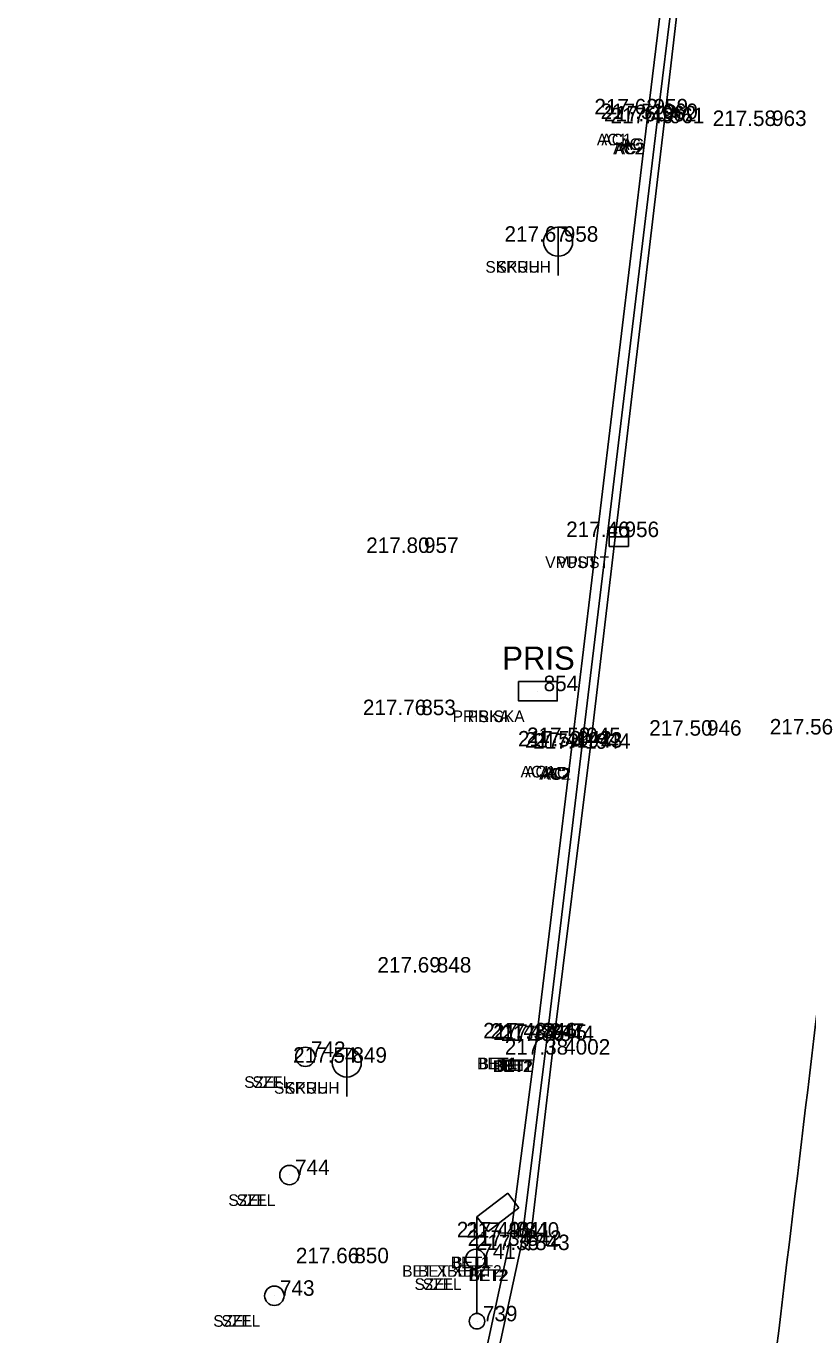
# Model space of a CAD drawing. Extents: x -471047 to -470889, y -1102859 to -1102000.
# Drawn here: x -471002.78 to -470982.59, y -1102598.73 to -1102564.92 of the extents above; entities that cross this region are included whole.
import ezdxf

# ---------------------------------------------------------------- set-up
doc = ezdxf.new("R2010")
doc.units = 0
for name, color, linetype in [('Vrstva 1', 7, 'Continuous'), ('Vrstva 23', 7, 'Continuous'), ('Vrstva 25', 7, 'Continuous'), ('Vrstva 34', 7, 'Continuous'), ('Vrstva 35', 7, 'Continuous'), ('Vrstva 36', 7, 'Continuous'), ('Vrstva 38', 7, 'Continuous'), ('Vrstva 5', 7, 'Continuous'), ('Vrstva 7', 7, 'Continuous'), ('Vrstva 8', 7, 'Continuous')]:
    doc.layers.add(name, color=color, linetype=linetype)

msp = doc.modelspace()

# ---------------------------------------------------------------- linework, layer by layer
at = {"layer": 'Vrstva 1'}
for points in [[(-471040.344, -1102858.385), (-471031.676, -1102846.187), (-471026.357, -1102838.629), (-471023.212, -1102833.975), (-471019.21, -1102827.465), (-471016.861, -1102823.272), (-471013.099, -1102815.912), (-471010.824, -1102810.955), (-471007.329, -1102802.292), (-471005.34, -1102796.515), (-471002.842, -1102787.838), (-471001.3, -1102780.997), (-471000.19, -1102774.713), (-470999.247, -1102768.204), (-470998.794, -1102764.784), (-470997.199, -1102751.812), (-470994.899, -1102732.807), (-470992.551, -1102713.262), (-470990.326, -1102694.887), (-470988.122, -1102676.57), (-470985.812, -1102657.305), (-470983.537, -1102638.407), (-470981.386, -1102620.622), (-470979.843, -1102608.014), (-470976.377, -1102579.253), (-470972.945, -1102550.69), (-470970.475, -1102530.206), (-470967.905, -1102508.801), (-470965.053, -1102485.131), (-470962.734, -1102465.9), (-470960.173, -1102444.812), (-470957.795, -1102425.103), (-470954.965, -1102401.839), (-470953.834, -1102392.574), (-470952.33, -1102379.985), (-470950.744, -1102366.853), (-470948.978, -1102352.106), (-470947.037, -1102335.844), (-470944.949, -1102318.462), (-470944.013, -1102310.745), (-470942.39, -1102297.267), (-470939.519, -1102273.45), (-470937.593, -1102257.43), (-470936.064, -1102244.81), (-470934.114, -1102228.634), (-470931.621, -1102207.856), (-470929.536, -1102190.857), (-470926.572, -1102166.31), (-470924.91, -1102152.663), (-470923.413, -1102140.333), (-470921.923, -1102127.669), (-470921.155, -1102120.084), (-470920.446, -1102109.574), (-470919.912, -1102099.137), (-470919.63, -1102088.981), (-470919.523, -1102081.193), (-470919.563, -1102070.395), (-470919.714, -1102064.236), (-470920.134, -1102054.704), (-470920.462, -1102047.615), (-470920.599, -1102044.52), (-470920.743, -1102041.873), (-470921.125, -1102034.455), (-470921.774, -1102030.337), (-470922.418, -1102027.787), (-470923.734, -1102023.93), (-470924.872, -1102021.434), (-470926.752, -1102018.182), (-470927.953, -1102016.45), (-470929.616, -1102014.424), (-470932.252, -1102011.756), (-470935.111, -1102009.425), (-470938.391, -1102007.371), (-470942.651, -1102005.401)], [(-471041.328, -1102857.18), (-471032.144, -1102844.242), (-471027.583, -1102837.763), (-471024.388, -1102833.028), (-471020.451, -1102826.6), (-471018.089, -1102822.378), (-471014.542, -1102815.445), (-471012.233, -1102810.418), (-471009.247, -1102803.108), (-471006.795, -1102796.098), (-471004.315, -1102787.532), (-471002.782, -1102780.723), (-471001.674, -1102774.458), (-471000.75, -1102768.095), (-471000.28, -1102764.601), (-470998.692, -1102751.741), (-470996.378, -1102732.635), (-470994.028, -1102713.058), (-470991.808, -1102694.749), (-470989.616, -1102676.447), (-470987.284, -1102657.013), (-470985.031, -1102638.272), (-470982.87, -1102620.431), (-470981.334, -1102607.933), (-470977.881, -1102579.263), (-470974.429, -1102550.492), (-470971.964, -1102530.054), (-470969.391, -1102508.607), (-470966.54, -1102484.984), (-470964.231, -1102465.853), (-470961.679, -1102444.752), (-470959.304, -1102425.078), (-470956.455, -1102401.634), (-470955.339, -1102392.489), (-470953.812, -1102379.71), (-470952.249, -1102366.808), (-470950.479, -1102352.023), (-470948.536, -1102335.868), (-470946.426, -1102318.233), (-470945.493, -1102310.531), (-470943.864, -1102297.013), (-470940.984, -1102273.071), (-470939.078, -1102257.195), (-470937.559, -1102244.684), (-470935.592, -1102228.353), (-470933.101, -1102207.653), (-470931.011, -1102190.57), (-470928.046, -1102166.021), (-470926.409, -1102152.578), (-470924.898, -1102140.121), (-470923.427, -1102127.544), (-470922.647, -1102119.826), (-470921.919, -1102109.229), (-470921.42, -1102099.134), (-470921.127, -1102089.016), (-470921.023, -1102081.453), (-470921.061, -1102070.468), (-470921.209, -1102064.314), (-470921.666, -1102053.966), (-470922.156, -1102043.345), (-470922.299, -1102039.934), (-470922.637, -1102034.36), (-470923.091, -1102031.241), (-470923.847, -1102028.247), (-470925.083, -1102024.594), (-470926.222, -1102022.086), (-470928.04, -1102018.943), (-470929.138, -1102017.357), (-470930.929, -1102015.175), (-470933.062, -1102013.049), (-470936.379, -1102010.368), (-470939.169, -1102008.662), (-470942.899, -1102006.906), (-470945.661, -1102005.908)], [(-471043.557, -1102855.955), (-471035.129, -1102844.026), (-471029.872, -1102836.499), (-471026.577, -1102831.578), (-471022.675, -1102825.415), (-471020.123, -1102821.053), (-471016.667, -1102814.59), (-471014.208, -1102809.45), (-471011.177, -1102802.451), (-471008.55, -1102795.333), (-471006.082, -1102787.209), (-471004.464, -1102780.376), (-471003.265, -1102774.167), (-471002.327, -1102767.948), (-471001.636, -1102762.527), (-471000.297, -1102751.605), (-470997.959, -1102732.524), (-470995.602, -1102712.802), (-470993.412, -1102694.623), (-470991.21, -1102676.17), (-470988.891, -1102656.857), (-470986.625, -1102638.083), (-470984.455, -1102620.195), (-470982.936, -1102607.733), (-470979.497, -1102579.223), (-470976.023, -1102550.279), (-470973.554, -1102529.822), (-470970.991, -1102508.497), (-470968.146, -1102484.787), (-470965.835, -1102465.72), (-470963.284, -1102444.529), (-470960.91, -1102424.942), (-470958.043, -1102401.343), (-470956.946, -1102392.356), (-470955.396, -1102379.408), (-470953.851, -1102366.636), (-470952.049, -1102351.733), (-470950.124, -1102335.611), (-470948.034, -1102318.083), (-470947.094, -1102310.328), (-470945.421, -1102296.51), (-470942.58, -1102272.848), (-470940.675, -1102256.948), (-470939.176, -1102244.526), (-470937.187, -1102228.174), (-470934.708, -1102207.467), (-470932.621, -1102190.433), (-470929.634, -1102165.778), (-470928.004, -1102152.415), (-470926.45, -1102139.595), (-470925.003, -1102127.418), (-470924.249, -1102119.695), (-470923.515, -1102109.093), (-470923.018, -1102099.069), (-470922.711, -1102088.911), (-470922.643, -1102081.356), (-470922.797, -1102070.414), (-470923.018, -1102064.454), (-470923.52, -1102053.203), (-470923.823, -1102047.529), (-470924.123, -1102041.506), (-470924.462, -1102037.486), (-470924.934, -1102031.904), (-470925.664, -1102028.672), (-470926.771, -1102025.506), (-470927.959, -1102022.914), (-470929.674, -1102020.028), (-470930.76, -1102018.498), (-470932.447, -1102016.478), (-470935.215, -1102013.816), (-470937.644, -1102011.98), (-470940.381, -1102010.371), (-470943.968, -1102008.669), (-470947.145, -1102007.524), (-470950.874, -1102006.74)], [(-471044.756, -1102855.056), (-471036.376, -1102843.177), (-471031.167, -1102835.741), (-471027.859, -1102830.8), (-471023.934, -1102824.593), (-471021.43, -1102820.312), (-471018.011, -1102813.91), (-471015.536, -1102808.75), (-471012.578, -1102801.897), (-471009.95, -1102794.77), (-471007.561, -1102786.914), (-471005.936, -1102780.074), (-471004.727, -1102773.818), (-471003.828, -1102767.827), (-471003.121, -1102762.345), (-471001.787, -1102751.467), (-470999.446, -1102732.348), (-470997.073, -1102712.539), (-470994.902, -1102694.521), (-470992.696, -1102676.023), (-470990.376, -1102656.68), (-470988.131, -1102638.071), (-470985.947, -1102620.018), (-470984.417, -1102607.512), (-470980.993, -1102579.08), (-470977.514, -1102550.137), (-470975.048, -1102529.649), (-470972.488, -1102508.37), (-470969.618, -1102484.508), (-470967.34, -1102465.669), (-470964.767, -1102444.39), (-470962.402, -1102424.781), (-470959.534, -1102401.193), (-470958.432, -1102392.151), (-470956.883, -1102379.208), (-470955.335, -1102366.424), (-470953.535, -1102351.506), (-470951.606, -1102335.399), (-470949.519, -1102317.94), (-470948.575, -1102310.159), (-470946.889, -1102296.144), (-470944.056, -1102272.618), (-470942.139, -1102256.659), (-470940.657, -1102244.341), (-470938.638, -1102227.749), (-470936.19, -1102207.298), (-470934.102, -1102190.255), (-470931.124, -1102165.639), (-470929.492, -1102152.254), (-470927.915, -1102139.252), (-470926.46, -1102127.103), (-470925.74, -1102119.604), (-470925.012, -1102108.913), (-470924.523, -1102099.054), (-470924.217, -1102088.866), (-470924.148, -1102081.334), (-470924.301, -1102070.391), (-470924.518, -1102064.43), (-470924.97, -1102054.435), (-470925.588, -1102041.569), (-470925.963, -1102035.313), (-470926.405, -1102032.225), (-470927.078, -1102029.198), (-470928.123, -1102026.148), (-470929.318, -1102023.558), (-470930.84, -1102020.97), (-470931.868, -1102019.515), (-470933.443, -1102017.605), (-470936.26, -1102014.885), (-470938.429, -1102013.255), (-470941.213, -1102011.639), (-470944.847, -1102009.927), (-470947.723, -1102008.912), (-470951.444, -1102008.161), (-470954.511, -1102007.931), (-470957.895, -1102008.041)]]:
    msp.add_spline(points, degree=3, dxfattribs=at)
at = {"layer": 'Vrstva 23'}
for p, q in [((-470990.338, -1102595.073), (-470991.133, -1102595.678)), ((-470990.048, -1102595.45), (-470990.338, -1102595.073)), ((-470990.846, -1102596.056), (-470990.048, -1102595.45)), ((-470991.133, -1102595.678), (-470991.133, -1102598.178)), ((-470991.133, -1102595.678), (-470990.846, -1102596.056))]:
    msp.add_line(p, q, dxfattribs=at)
msp.add_lwpolyline([(-470990.06, -1102581.851), (-470989.06, -1102581.851), (-470989.06, -1102582.351), (-470990.06, -1102582.351)], close=True, dxfattribs=at)
for centre, radius in [((-470995.566, -1102591.547), 0.25), ((-470995.978, -1102594.602), 0.25), ((-470991.173, -1102596.77), 0.25), ((-470996.367, -1102597.721), 0.25), ((-470991.133, -1102598.378), 0.2)]:
    msp.add_circle(centre, radius, dxfattribs=at)
at = {"layer": 'Vrstva 25'}
for p, q in [((-470989.037, -1102570.866), (-470989.037, -1102570.116)), ((-470989.037, -1102570.866), (-470989.037, -1102571.366)), ((-470987.722, -1102577.866), (-470987.722, -1102578.366)), ((-470987.222, -1102577.866), (-470987.722, -1102577.866)), ((-470987.222, -1102578.366), (-470987.222, -1102577.866)), ((-470987.722, -1102578.116), (-470987.222, -1102578.116)), ((-470987.722, -1102578.366), (-470987.222, -1102578.366)), ((-470994.495, -1102592.071), (-470994.495, -1102591.321)), ((-470994.495, -1102592.071), (-470994.495, -1102592.571))]:
    msp.add_line(p, q, dxfattribs=at)
for centre in [(-470989.037, -1102570.491), (-470994.495, -1102591.696)]:
    msp.add_circle(centre, 0.375, dxfattribs=at)
at = {"layer": 'Vrstva 34'}
for p, q in [((-470986.72, -1102567.2), (-470986.72, -1102567.2)), ((-470986.51, -1102567.38), (-470986.51, -1102567.38)), ((-470986.47, -1102567.32), (-470986.47, -1102567.32)), ((-470986.3, -1102567.43), (-470986.3, -1102567.43)), ((-470983.66, -1102567.5), (-470983.66, -1102567.5)), ((-470989.04, -1102570.49), (-470989.04, -1102570.49)), ((-470987.47, -1102578.12), (-470987.47, -1102578.12)), ((-470992.65, -1102578.53), (-470992.65, -1102578.53)), ((-470989.56, -1102582.1), (-470989.56, -1102582.1)), ((-470992.72, -1102582.72), (-470992.72, -1102582.72)), ((-470988.46, -1102583.44), (-470988.46, -1102583.44)), ((-470985.34, -1102583.25), (-470985.34, -1102583.25)), ((-470988.69, -1102583.53), (-470988.69, -1102583.53)), ((-470988.42, -1102583.56), (-470988.42, -1102583.56)), ((-470988.21, -1102583.59), (-470988.21, -1102583.59)), ((-470992.32, -1102589.37), (-470992.32, -1102589.37)), ((-470989.59, -1102591.07), (-470989.59, -1102591.07)), ((-470989.4, -1102591.08), (-470989.4, -1102591.08)), ((-470989.33, -1102591.11), (-470989.33, -1102591.11)), ((-470989.15, -1102591.14), (-470989.15, -1102591.14)), ((-470995.57, -1102591.55), (-470995.57, -1102591.55)), ((-470989.03, -1102591.49), (-470989.03, -1102591.49)), ((-470994.5, -1102591.7), (-470994.5, -1102591.7)), ((-470995.98, -1102594.6), (-470995.98, -1102594.6)), ((-470990.27, -1102596.21), (-470990.27, -1102596.21)), ((-470990.05, -1102596.22), (-470990.05, -1102596.22)), ((-470989.99, -1102596.43), (-470989.99, -1102596.43)), ((-470989.78, -1102596.54), (-470989.78, -1102596.54)), ((-470994.45, -1102596.88), (-470994.45, -1102596.88)), ((-470991.17, -1102596.77), (-470991.17, -1102596.77)), ((-470996.37, -1102597.72), (-470996.37, -1102597.72)), ((-470991.13, -1102598.38), (-470991.13, -1102598.38))]:
    msp.add_line(p, q, dxfattribs=at)
at = {"layer": 'Vrstva 5'}
for p, q in [((-470986.297, -1102567.429), (-470984.977, -1102556.019)), ((-470988.205, -1102583.592), (-470986.297, -1102567.429)), ((-470989.149, -1102591.137), (-470988.205, -1102583.592)), ((-470989.784, -1102596.538), (-470989.149, -1102591.137)), ((-470989.99, -1102596.434), (-470989.784, -1102596.538))]:
    msp.add_line(p, q, dxfattribs=at)
at = {"layer": 'Vrstva 7'}
for p, q in [((-470986.719, -1102567.201), (-470985.359, -1102555.993)), ((-470988.687, -1102583.533), (-470986.719, -1102567.201)), ((-470989.593, -1102591.074), (-470988.687, -1102583.533)), ((-470990.266, -1102596.212), (-470989.593, -1102591.074)), ((-470992.241, -1102605.417), (-470990.266, -1102596.212))]:
    msp.add_line(p, q, dxfattribs=at)
at = {"layer": 'Vrstva 8'}
for p, q in [((-470986.467, -1102567.319), (-470985.101, -1102555.977)), ((-470988.422, -1102583.556), (-470986.467, -1102567.319)), ((-470989.329, -1102591.107), (-470988.422, -1102583.556)), ((-470989.99, -1102596.434), (-470989.329, -1102591.107)), ((-470992.058, -1102605.966), (-470989.99, -1102596.434))]:
    msp.add_line(p, q, dxfattribs=at)

# ---------------------------------------------------------------- texts
at = {"layer": 'Vrstva 23'}
msp.add_text('PRIS', height=0.6, dxfattribs=at).set_placement((-470990.48, -1102581.548))
at = {"layer": 'Vrstva 35'}
for s, p in [('AC1', (-470988.037, -1102568)), ('AC1', (-470987.92, -1102568)), ('AC', (-470987.459, -1102568.12)), ('AC', (-470987.384, -1102568.12)), ('AC2', (-470987.616, -1102568.23)), ('AC2', (-470987.575, -1102568.23)), ('SKRUH', (-470990.915, -1102571.29)), ('SKRUH', (-470990.629, -1102571.29)), ('VPUST', (-470989.37, -1102578.92)), ('VPUST', (-470989.059, -1102578.92)), ('PRISKA', (-470991.76, -1102582.9)), ('PRISKA', (-470991.374, -1102582.9)), ('AC1', (-470990.007, -1102584.33)), ('AC1', (-470989.89, -1102584.33)), ('AC2', (-470989.526, -1102584.39)), ('AC2', (-470989.485, -1102584.39)), ('AC', (-470989.409, -1102584.36)), ('AC', (-470989.334, -1102584.36)), ('BET1', (-470991.132, -1102591.87)), ('BET1', (-470991.09, -1102591.87)), ('BET2', (-470990.725, -1102591.94)), ('BET2', (-470990.691, -1102591.94)), ('BET', (-470990.63, -1102591.91)), ('BET', (-470990.469, -1102591.91)), ('SZEL', (-470997.145, -1102592.35)), ('SZEL', (-470996.934, -1102592.35)), ('SKRUH', (-470996.375, -1102592.5)), ('SKRUH', (-470996.089, -1102592.5)), ('SZEL', (-470997.555, -1102595.4)), ('SZEL', (-470997.344, -1102595.4)), ('BET XBET2', (-470993.065, -1102597.23)), ('BET XBET2', (-470992.656, -1102597.23)), ('BET1', (-470991.812, -1102597.01)), ('BET1', (-470991.77, -1102597.01)), ('SZEL', (-470992.745, -1102597.57)), ('SZEL', (-470992.534, -1102597.57)), ('BET2', (-470991.355, -1102597.34)), ('BET2', (-470991.321, -1102597.34)), ('SZEL', (-470997.945, -1102598.52)), ('SZEL', (-470997.734, -1102598.52))]:
    msp.add_text(s, height=0.3, dxfattribs=at).set_placement(p)
at = {"layer": 'Vrstva 36'}
for s, p in [(' 959', (-470986.72, -1102567.2)), (' 962', (-470986.51, -1102567.38)), (' 960', (-470986.47, -1102567.32)), (' 961', (-470986.3, -1102567.43)), (' 963', (-470983.66, -1102567.5)), (' 958', (-470989.04, -1102570.49)), (' 956', (-470987.47, -1102578.12)), (' 957', (-470992.65, -1102578.53)), (' 854', (-470989.56, -1102582.1)), (' 853', (-470992.72, -1102582.72)), (' 945', (-470988.46, -1102583.44)), (' 946', (-470985.34, -1102583.25)), (' 942', (-470988.69, -1102583.53)), (' 943', (-470988.42, -1102583.56)), (' 944', (-470988.21, -1102583.59)), (' 848', (-470992.32, -1102589.37)), (' 846', (-470989.59, -1102591.07)), (' 847', (-470989.4, -1102591.08)), (' 845', (-470989.33, -1102591.11)), (' 844', (-470989.15, -1102591.14)), (' 742', (-470995.57, -1102591.55)), (' 4002', (-470989.03, -1102591.49)), (' 849', (-470994.5, -1102591.7)), (' 744', (-470995.98, -1102594.6)), (' 841', (-470990.27, -1102596.21)), (' 840', (-470990.05, -1102596.22)), (' 842', (-470989.99, -1102596.43)), (' 843', (-470989.78, -1102596.54)), (' 850', (-470994.45, -1102596.88)), (' 741', (-470991.17, -1102596.77)), (' 743', (-470996.37, -1102597.72)), (' 739', (-470991.13, -1102598.38))]:
    msp.add_text(s, height=0.4, dxfattribs=at).set_placement(p)
at = {"layer": 'Vrstva 38'}
for s, p in [('217.62 ', (-470988.101, -1102567.2)), ('217.51 ', (-470987.94, -1102567.32)), ('217.60 ', (-470987.853, -1102567.38)), ('217.49 ', (-470987.684, -1102567.43)), ('217.58 ', (-470985.044, -1102567.5)), ('217.67 ', (-470990.423, -1102570.49)), ('217.46 ', (-470988.83, -1102578.12)), ('217.80 ', (-470993.993, -1102578.53)), ('217.76 ', (-470994.08, -1102582.72)), ('217.52 ', (-470989.841, -1102583.44)), ('217.50 ', (-470986.683, -1102583.25)), ('217.56 ', (-470983.57, -1102583.22)), ('217.53 ', (-470990.073, -1102583.53)), ('217.41 ', (-470989.89, -1102583.56)), ('217.41 ', (-470989.68, -1102583.59)), ('217.69 ', (-470993.704, -1102589.37)), ('217.48 ', (-470990.974, -1102591.07)), ('217.47 ', (-470990.783, -1102591.08)), ('217.34 ', (-470990.712, -1102591.11)), ('217.36 ', (-470990.51, -1102591.14)), ('217.38 ', (-470990.414, -1102591.49)), ('217.54 ', (-470995.882, -1102591.7)), ('217.49 ', (-470991.654, -1102596.21)), ('217.46 ', (-470991.41, -1102596.22)), ('217.34 ', (-470991.372, -1102596.43)), ('217.35 ', (-470991.164, -1102596.54)), ('217.66 ', (-470995.81, -1102596.88))]:
    msp.add_text(s, height=0.4, dxfattribs=at).set_placement(p)

doc.saveas('drawing.dxf')
